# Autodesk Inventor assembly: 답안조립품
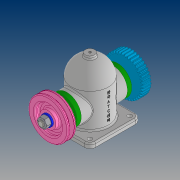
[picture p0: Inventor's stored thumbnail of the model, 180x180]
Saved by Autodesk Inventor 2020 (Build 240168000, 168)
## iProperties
Created: 2021-08
Part Number: 답안조립품
Document SubType Name: Assembly
Designer: PC312-
Author: PC312-
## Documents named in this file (14)
- C:\Users\PC312-\Desktop\710809V1003\답안조립품.iam
- C:\Users\PC312-\Desktop\710809V1003\본체.ipt
- C:\Users\PC312-\Desktop\710809V1003\커버.ipt
- C:\Users\PC312-\Desktop\710809V1003\베어링 6203.ipt
- C:\Users\PC312-\Desktop\710809V1003\축.ipt
- C:\Users\PC312-\Desktop\710809V1003\키 5x5x12.ipt
- C:\Users\PC312-\Desktop\710809V1003\부시.ipt
- C:\Users\PC312-\Desktop\710809V1003\오일 실 26 38 8.ipt
- C:\Users\PC312-\Desktop\710809V1003\볼트 M4.ipt
- C:\Users\PC312-\Desktop\710809V1003\V-벨트풀리.ipt
- V-벨트풀리.ipt
- C:\Users\PC312-\Desktop\710809V1003\와셔 12x24.ipt
- C:\Users\PC312-\Desktop\710809V1003\너트 M12x1.25.ipt
- C:\Users\PC312-\Desktop\710809V1003\스퍼기어.ipt
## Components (1 placed, 1 different names)
1. V-벨트풀리:1
